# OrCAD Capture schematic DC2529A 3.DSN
size Custom
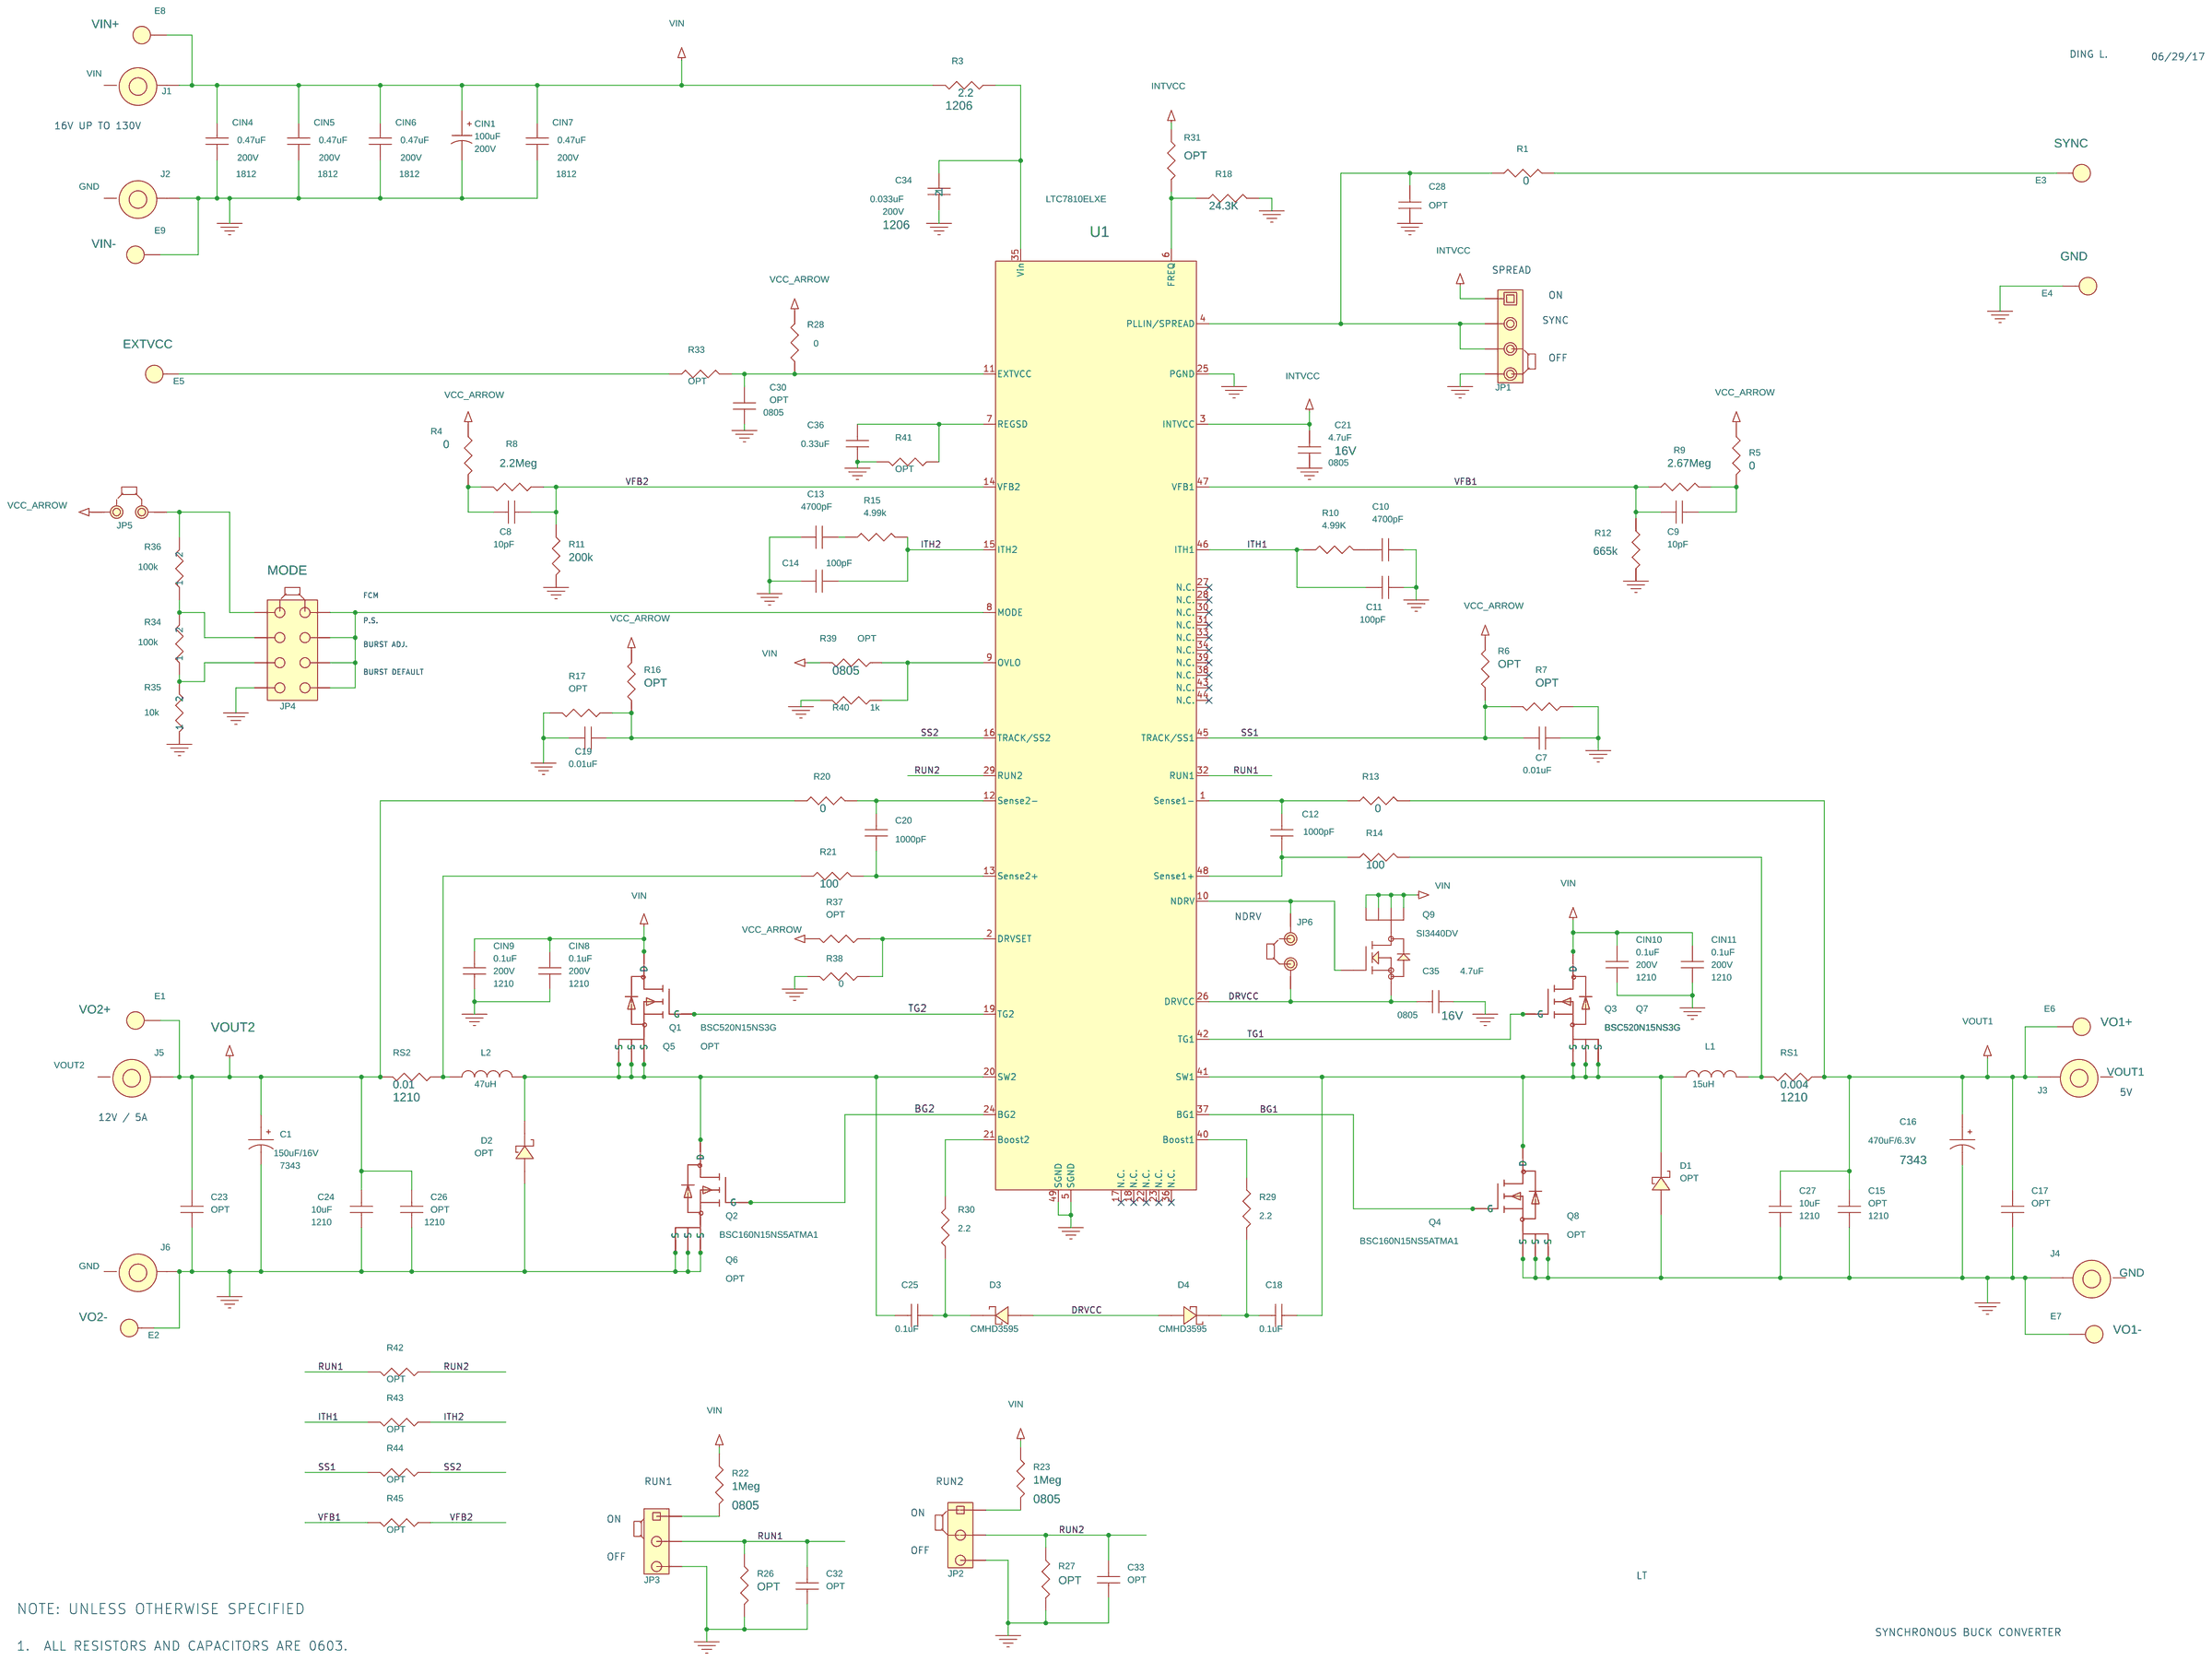
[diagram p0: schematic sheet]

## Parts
C1  150uF/16V  [7343]
C7  0.01uF  [0603]
C8  10pF  [0603]
C9  10pF  [0603]
C10  4700pF  [0603]
C11  100pF  [0603]
C12  1000pF  [0603]
C13  4700pF  [0603]
C14  100pF  [0603]
C15  OPT  [1210]
C16  470uF/6.3V  [7343]
C17  OPT  [0603]
C18  0.1uF  [0603]
C19  0.01uF  [0603]
C20  1000pF  [0603]
C21  4.7uF  [0805]
C23  OPT  [0603]
C24  10uF  [1210]
C25  0.1uF  [0603]
C26  OPT  [1210]
C27  10uF  [1210]
C28  OPT  [0603]
C30  OPT  [0805]
C32  OPT  [0603]
C33  OPT  [0603]
C34  0.033uF  [1206]
C35  4.7uF  [0805]
C36  0.33uF  [0603]
CIN1  100uF  [CAP\NIC\16X20]
CIN4  0.47uF  [1812]
CIN5  0.47uF  [1812]
CIN6  0.47uF  [1812]
CIN7  0.47uF  [1812]
CIN8  0.1uF  [1210]
CIN9  0.1uF  [1210]
CIN10  0.1uF  [1210]
CIN11  0.1uF  [1210]
D1  OPT  [POWER-DI-123]
D2  OPT  [POWER-DI-123]
D3  CMHD3595  [SOD-123]
D4  CMHD3595  [SOD-123]
E1  VO2+  [MILLMAX-2501-2]
E2  VO2-  [MILLMAX-2501-2]
E3  SYNC  [MILLMAX-2501-2]
E4  GND  [MILLMAX-2501-2]
E5  EXTVCC  [MILLMAX-2501-2]
E6  VO1+  [MILLMAX-2501-2]
E7  VO1-  [MILLMAX-2501-2]
E8  VIN+  [MILLMAX-2501-2]
E9  VIN-  [MILLMAX-2501-2]
J1  VIN  [BANANA-JACK]
J2  GND  [BANANA-JACK]
J3  VOUT1  [BANANA-JACK]
J4  GND  [BANANA-JACK]
J5  VOUT2  [BANANA-JACK]
J6  GND  [BANANA-JACK]
JP1  4 Pins 2mm Ctrs.  [SIP\4P\2MM]
JP2  3 Pins 2mm Ctrs.  [commcon2802s03g2]
JP3  3 Pins 2mm Ctrs.  [commcon2802s03g2]
JP4  MODE  [HDR2X4_2MM]
JP5  2 Pins 2mm Ctrs.  [SIP\2P\2MM]
JP6  2 Pins 2mm Ctrs.  [SIP\2P\2MM]
L1  15uH  [IND-744363]
L2  47uH  [IND-744363]
Q1  BSC520N15NS3G  [WPACKV]
Q2  BSC160N15NS5ATMA1  [WPACKV]
Q3  BSC520N15NS3G  [WPACKV]
Q4  BSC160N15NS5ATMA1  [WPACKV]
Q5  OPT  [WPACKV]
Q6  OPT  [WPACKV]
Q7  BSC520N15NS3G  [WPACKV]
Q8  OPT  [WPACKV]
Q9  SI3440DV  [TSOP6]
R1  0  [0603]
R3  2.2  [1206]
R4  0  [0603]
R5  0  [0603]
R6  OPT  [0603]
R7  OPT  [0603]
R8  2.2Meg  [0603]
R9  2.67Meg  [0603]
R10  4.99K  [0603]
R11  200k  [0603]
R12  665k  [0603]
R13  0  [0603]
R14  100  [0603]
R15  4.99k  [0603]
R16  OPT  [0603]
R17  OPT  [0603]
R18  24.3K  [0603]
R20  0  [0603]
R21  100  [0603]
R22  1Meg  [0805]
R23  1Meg  [0805]
R26  OPT  [0603]
R27  OPT  [0603]
R28  0  [0603]
R29  2.2  [0603]
R30  2.2  [0603]
R31  OPT  [0603]
R33  OPT  [0603]
R34  100k  [0603]
R35  10k  [0603]
R36  100k  [0603]
R37  OPT  [0603]
R38  0  [0603]
R39  OPT  [0805]
R40  1k  [0603]
R41  OPT  [0603]
R42  OPT  [0603]
R43  OPT  [0603]
R44  OPT  [0603]
R45  OPT  [0603]
RS1  0.004  [1210]
RS2  0.01  [1210]
U1  LTC7810ELXE  [LQFP-7X7]
XJP1  2mm Ctrs.
XJP2  2mm Ctrs.
XJP3  2mm Ctrs.
XJP4  SHUNT  [NONE]
XJP5  SHUNT  [NONE]
XJP6  SHUNT  [NONE]

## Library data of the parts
C1 = CAP_POL: MANUFACTURING: 10TPE330M; VOLTAGE: 10V
C7-C15 C17-C20 C23-C28 C30 C32 C33 C36 = CAP_NP_0: VOLTAGE: ( Opt. )
C16 = CAP_POL
C21 C35 = CAP_NP_0: 1PART: 16V; VOLTAGE: ( Opt. )
C34 = CAP_NP_1: CAP, 1206 0.033uF 20% 200V; Part Number: VISHAY VJ1206Y333MXCAT; Voltage: 200V
CIN1 = 4TPE220MF: CAP, 100uF 20% 200V ELEC; 1st Part Field: 200V; 5th Part Field: 50CE330LX; Part Number: NIC NRB-XS101M200V16x20TBF
CIN4-CIN7 = EMK212BJ475MG: CAP, 1812 .47uF 10% 200V X7R; 1st Part Field: 200V; Part Number: KEMET C1812X474K2RACTU
CIN8-CIN11 = CAP_NP_4: CAP, 1210 0.1uF 10% 200V X7R; Part Number: AVX 12102C104KAT2A; Voltage: 200V
D1 = DIODE_SCHOTTKY31_6
D2 = DIODE_SCHOTTKY31_5
D3 D4 = DIODE_SCHOTTKY31_7
E1-E9 = TP_0
J1 J3 = E_7
J2 J4-J6 = E_6
JP1 = Samtec_TMM-104-02-L-S: HEADER, 4PIN 2mm; 10th Part Field: 180; 11th Part Field: 90; 13tht Part Field: PHASEMD; 9th Part Field: 120; Part Number: SULLINS NRPN041PAEN-RC
JP2 JP3 = Commcon2802s03g2: 11th Part Field: OFF; 12th Part Field: RUN; 9th Part Field: ON
JP4 = hdr2X4_2MM: HEADER, DOUBLE ROW 2X4 2mm; Part Number: SULLINS NRPN042PAEN-RC
JP5 = Samtec_TMM-102-02-L-S_1: HEADER, 2PIN, 2mm; 7th Part Field: VO2 SELECT; 9th Part Field: 2.5V; Part Number: SULLINS NRPN021PAEN-RC
JP6 = Samtec_TMM-102-02-L-S: HEADER, 2PIN, 2mm; 7th Part Field: VO2 SELECT; 9th Part Field: 2.5V; Part Number: SULLINS NRPN021PAEN-RC
L1 = INDUCTOR: manufacturing: Coilcraft SER1360-472KL
L2 = INDUCTOR: manufacturing: Coilcraft SER1360-802KL
Q1-Q8 = MOS_FET_0: XSTR, N-CHANNEL DMOS FET; Part Number: INFINEON BSC520N15NS3G
Q9 = MOSFET_N-DIODE-A-TSOP6_0
R1 R3-R18 R20-R23 R26-R31 R33 R37-R45 RS1 RS2 = R_1: %: 0.1%
R34 = R_2: RES, 0603 100K OHMS 5% 1/10W; Part Number: VISHAY CRCW0603100KJNEB
R35 = R: RES, 0603 10K OHMS 5% 1/10W; Part Number: VISHAY CRCW060310K0JNEA; Tol: 5%
R36 = R_1: RES, 0603 100K OHMS 5% 1/10W; Part Number: VISHAY CRCW0603100KJNEB
U1 = LTC3890EUFD_53
XJP1-XJP3 = CommconCCIJ2MM-138G
XJP4-XJP6 = Samtec_2SN-BK-G: SHUNT, 2mm; Part Number: SAMTEC 2SN-BK-G

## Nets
GND: C1.2 C7.1 C10.1 C11.1 C13.1 C14.1 C15.1 C16.2 C17.1 C19.2 C21.1 C23.1 C24.1 C26.1 C27.1 C28.1 C30.1 C32.1 C33.1 C34.2 C35.1 C36.1 CIN1.2 CIN4.2 CIN5.2 CIN6.2 CIN7.2 CIN8.2 CIN9.2 CIN10.2 CIN11.2 D1.2(ANODE) D2.2(ANODE) E2.1(A) E4.1(A) E7.1(A) E9.1(A) J2.1(A) J4.1(A) J6.1(A) JP1.4 JP2.3 JP3.3 JP4.7 Q2.1(S) Q2.2(S) Q2.3(S) Q4.1(S) Q4.2(S) Q4.3(S) Q6.1(S) Q6.2(S) Q6.3(S) Q8.1(S) Q8.2(S) Q8.3(S) R7.2 R11.2 R12.1 R17.1 R18.2 R26.2 R27.2 R35.1 R38.2 R40.2 R41.2 U1.5(SGND) U1.25(PGND) U1.49(SGND)
VIN: CIN1.1 CIN4.1 CIN5.1 CIN6.1 CIN7.1 CIN8.1 CIN9.1 CIN10.1 CIN11.1 E8.1(A) J1.1(A) Q1.5(D) Q3.5(D) Q5.5(D) Q7.5(D) Q9.1 Q9.2 Q9.5 Q9.6 R3.2 R22.1 R23.1 R39.2
BG1: Q4.4(G) Q8.4(G) U1.37(BG1)
BG2: Q2.4(G) Q6.4(G) U1.24(BG2)
DRVCC: C35.2 D3.2(ANODE) D4.2(ANODE) JP6.1 Q9.4 U1.26(DRVCC)
INTVCC: C21.2 JP1.1 JP5.1 R31.1 R37.2 U1.3(INTVCC)
ITH1: C11.2 R10.1 R43.2 U1.46(ITH1)
ITH2: C14.2 R15.1 R43.1 U1.15(ITH2)
RUN1: C32.2 JP3.2 R26.1 R42.2 U1.32(RUN1)
RUN2: C33.2 JP2.2 R27.1 R42.1 U1.29(RUN2)
SS1: C7.2 R6.2 R7.1 R44.2 U1.45(TRACK/SS1)
SS2: C19.1 R16.2 R17.2 R44.1 U1.16(TRACK/SS2)
TG1: Q3.4(G) Q7.4(G) U1.42(TG1)
TG2: Q1.4(G) Q5.4(G) U1.19(TG2)
VFB1: C9.1 R9.2 R12.2 R45.2 U1.47(VFB1)
VFB2: C8.2 R8.1 R11.1 R45.1 U1.14(VFB2)
Vout1: C15.2 C16.1 C17.2 C27.2 E6.1(A) J3.1(A) R5.2 R13.2 R16.1 RS1.1
Vout2: C1.1 C23.2 C24.2 C26.2 E1.1(A) J5.1(A) R4.1 R6.1 R20.1 R28.2 RS2.2
N16713609: C34.1 R3.1 U1.35(Vin)
N16718537: C30.2 R28.1 R33.2 U1.11(EXTVCC)
N16720967: C25.2 D2.1(CATHODE) L2.2 Q1.1(S) Q1.2(S) Q1.3(S) Q2.5(D) Q5.1(S) Q5.2(S) Q5.3(S) Q6.5(D) U1.20(SW2)
N16723286: C25.1 D3.1(CATHODE) R30.1
N16724420: C18.1 D1.1(CATHODE) L1.1 Q3.1(S) Q3.2(S) Q3.3(S) Q4.5(D) Q7.1(S) Q7.2(S) Q7.3(S) Q8.5(D) U1.41(SW1)
N16725833: C20.1 R21.2 U1.13(Sense2+)
N16746092: C8.1 R4.2 R8.2
N16823491: L1.2 R14.2 RS1.2
N16832061: R18.1 R31.2 U1.6(FREQ)
N16860960: C12.2 R13.1 U1.1(Sense1-)
N16860970: C12.1 R14.1 U1.48(Sense1+)
N16872533: C20.2 R20.2 U1.12(Sense2-)
N16881627: R30.2 U1.21(Boost2)
N16882586: C18.2 D4.1(CATHODE) R29.2
N16882661: R29.1 U1.40(Boost1)
N16910782: C28.2 JP1.2 JP1.3 R1.1 U1.4(PLLIN/SPREAD)
N16911189: C9.2 R5.1 R9.1
N17044013: E3.1(A) R1.2
N17188004: JP6.2 Q9.3 U1.10(NDRV)
N17191034: JP4.2 JP4.4 JP4.6 JP4.8 U1.8(MODE)
N17191549: R37.1 R38.1 U1.2(DRVSET)
N17192126: R39.1 R40.1 U1.9(OVLO)
N17192667: C36.2 R41.1 U1.7(REGSD)
N17195622: L2.1 R21.1 RS2.1
N17204262: JP4.1 JP5.2 R36.2
N17204323: JP4.5 R34.1 R35.2
N17204325: JP4.3 R34.2 R36.1
N17219876: C13.2 R15.2
N17243224: E5.1(A) R33.1
N17263661: JP3.1 R22.2
N17263674: JP2.1 R23.2
N17279439: C10.2 R10.2

Not connected (* = marked no-connect by the designer): U1 17(N.C.)* 18(N.C.)* 22(N.C.)* 23(N.C.)* 27(N.C.)* 28(N.C.)* 30(N.C.)* 31(N.C.)* 33(N.C.)* 34(N.C.)* 36(N.C.)* 38(N.C.)* 39(N.C.)* 43(N.C.)* 44(N.C.)*

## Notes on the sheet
- DING L.
- 06/29/17
- 16V UP TO 130V
- SPREAD
- ON
- SYNC
- OFF
- FCM
- P.S.
- BURST ADJ.
- BURST DEFAULT
- NDRV
- 5V
- 12V / 5A
- RUN1
- RUN2
- ON
- ON
- OFF
- OFF
- LT
- NOTE: UNLESS OTHERWISE SPECIFIED
- SYNCHRONOUS BUCK CONVERTER
- 1.  ALL RESISTORS AND CAPACITORS ARE 0603.
